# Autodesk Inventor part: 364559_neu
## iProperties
Created: 2006-10
Part Number: 364559_neu
Material: 1.0120.01
Description: Distanzplatte
Document SubType Name: Modeling
Designer: OSchmidt
Density: 7.84 g/cm^3
Mass: 25.088 g
Surface Area: 14.56 cm^2
Volume: 3.2 cm^3
Author: Natti_01
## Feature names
1. Extrusion2
